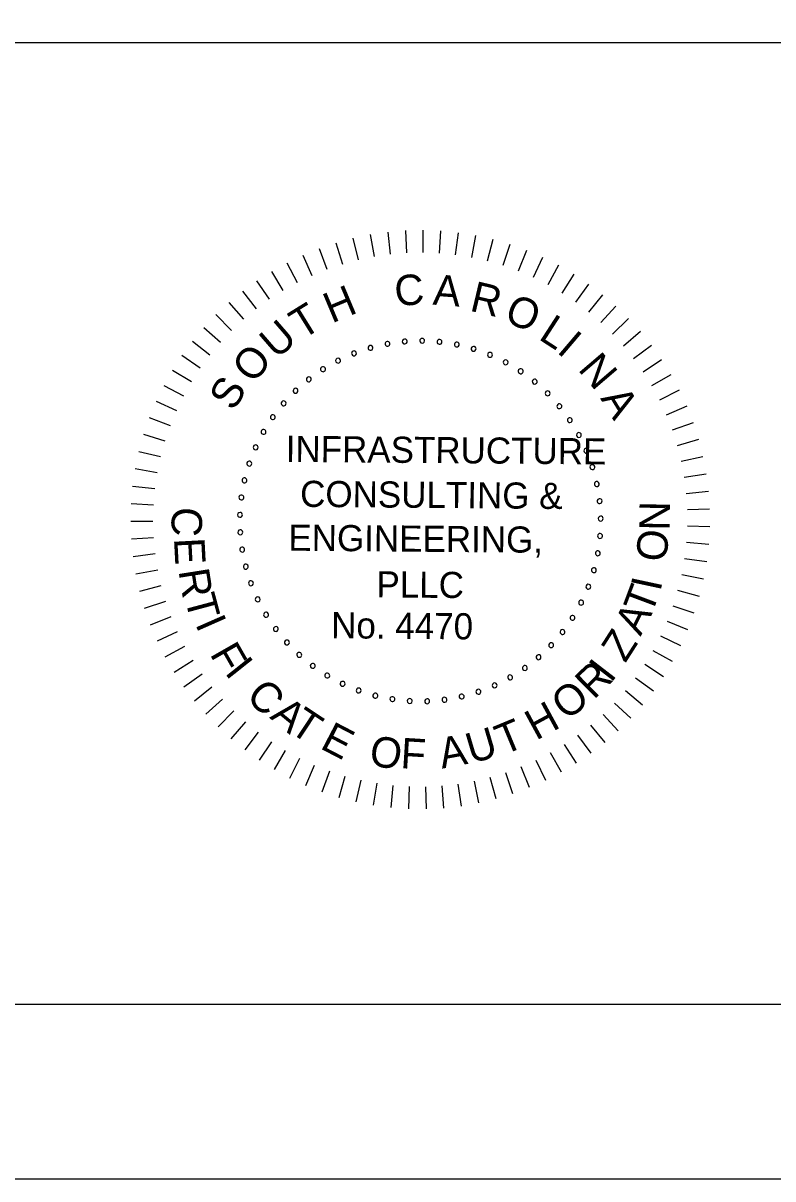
# Model space of a CAD drawing. Extents: x -121.2 to -24.9, y 6.4 to 65.9.
# Drawn here: x -53.97 to -48.25, y 6.35 to 15.17 of the extents above; entities that cross this region are included whole.
import ezdxf

# ---------------------------------------------------------------- set-up
doc = ezdxf.new("R2010")
doc.units = 0
for name, color, linetype in [('BR_BORDER LINES', 7, 'Continuous'), ('BR_TEXT', 7, 'Continuous'), ('Level 31', 7, 'Continuous')]:
    doc.layers.add(name, color=color, linetype=linetype)

msp = doc.modelspace()

# ---------------------------------------------------------------- linework, layer by layer
at = {"layer": 'BR_BORDER LINES'}
for p, q in [((-60.8035, 15.017), (-46.4963, 15.017)), ((-116.2718, 7.6833), (-26.4955, 7.6833))]:
    msp.add_line(p, q, dxfattribs=at)
at = {"layer": 'BR_TEXT'}
for p, q in [((-51.0538, 13.583), (-51.0448, 13.4135)), ((-50.9192, 13.5858), (-50.9206, 13.4161)), ((-50.7847, 13.5805), (-50.7964, 13.4111)), ((-51.583, 13.4903), (-51.5333, 13.3279)), ((-51.453, 13.5255), (-51.4134, 13.3604)), ((-51.3212, 13.5528), (-51.2917, 13.3856)), ((-51.188, 13.572), (-51.1687, 13.4033)), ((-50.6507, 13.5669), (-50.6728, 13.3985)), ((-50.5179, 13.5452), (-50.5502, 13.3785)), ((-50.3866, 13.5154), (-50.429, 13.351)), ((-51.7105, 13.4471), (-51.651, 13.2881)), ((-50.2574, 13.4777), (-50.3097, 13.3162)), ((-50.1307, 13.4322), (-50.1927, 13.2741)), ((-51.9565, 13.338), (-51.8781, 13.1874)), ((-51.8352, 13.3963), (-51.7661, 13.2412)), ((-50.007, 13.379), (-50.0786, 13.225)), ((-49.8868, 13.3184), (-49.9676, 13.1691)), ((-52.0741, 13.2724), (-51.9867, 13.1268)), ((-49.7705, 13.2506), (-49.8603, 13.1065)), ((-52.1874, 13.1997), (-52.0913, 13.0598)), ((-49.6586, 13.1758), (-49.757, 13.0374)), ((-52.2961, 13.1203), (-52.1916, 12.9865)), ((-49.5514, 13.0943), (-49.658, 12.9622)), ((-52.3997, 13.0344), (-52.2873, 12.9072)), ((-49.4494, 13.0064), (-49.5639, 12.8811)), ((-52.498, 12.9423), (-52.378, 12.8222)), ((-49.3529, 12.9125), (-49.4749, 12.7944)), ((-52.5904, 12.8445), (-52.4633, 12.7319)), ((-49.2624, 12.8129), (-49.3913, 12.7024)), ((-52.6767, 12.7411), (-52.543, 12.6365)), ((-49.178, 12.708), (-49.3135, 12.6056)), ((-52.7565, 12.6327), (-52.6167, 12.5364)), ((-52.8296, 12.5197), (-52.6841, 12.4321)), ((-49.1003, 12.5981), (-49.2417, 12.5041)), ((-49.0294, 12.4836), (-49.1763, 12.3985)), ((-52.8956, 12.4024), (-52.7451, 12.3238)), ((-48.9656, 12.3651), (-49.1174, 12.289)), ((-52.9544, 12.2812), (-52.7994, 12.212)), ((-48.9091, 12.2429), (-49.0653, 12.1762)), ((-53.0057, 12.1568), (-52.8467, 12.0971)), ((-48.8602, 12.1175), (-49.0201, 12.0604)), ((-53.0493, 12.0294), (-52.887, 11.9795)), ((-48.819, 11.9893), (-48.9821, 11.9421)), ((-53.085, 11.8996), (-52.92, 11.8597)), ((-48.7858, 11.8588), (-48.9514, 11.8217)), ((-53.1128, 11.7679), (-52.9456, 11.7381)), ((-48.7605, 11.7266), (-48.9281, 11.6996)), ((-53.1325, 11.6347), (-52.9638, 11.6152)), ((-48.7433, 11.5931), (-48.9123, 11.5764)), ((-53.144, 11.5006), (-52.9744, 11.4914)), ((-48.7344, 11.4588), (-48.904, 11.4524)), ((-53.1473, 11.366), (-52.9775, 11.3672)), ((-48.7336, 11.3241), (-48.9033, 11.3281)), ((-53.1424, 11.2314), (-52.973, 11.243)), ((-48.741, 11.1897), (-48.9102, 11.2041)), ((-53.1294, 11.0975), (-52.961, 11.1193)), ((-48.7566, 11.056), (-48.9246, 11.0806)), ((-53.1081, 10.9645), (-52.9414, 10.9966)), ((-48.7804, 10.9235), (-48.9465, 10.9583)), ((-53.0788, 10.8331), (-52.9144, 10.8753)), ((-53.0416, 10.7037), (-52.88, 10.7559)), ((-48.8121, 10.7927), (-48.9759, 10.8376)), ((-48.8518, 10.664), (-49.0125, 10.7188)), ((-52.9966, 10.5769), (-52.8384, 10.6388)), ((-48.8993, 10.538), (-49.0563, 10.6025)), ((-52.9438, 10.453), (-52.7898, 10.5244)), ((-52.8837, 10.3326), (-52.7343, 10.4132)), ((-48.9543, 10.4152), (-49.1072, 10.4891)), ((-49.0168, 10.2959), (-49.1648, 10.379)), ((-52.8163, 10.216), (-52.6721, 10.3057)), ((-49.0863, 10.1807), (-49.2291, 10.2727)), ((-52.7419, 10.1038), (-52.6034, 10.2021)), ((-49.1628, 10.0699), (-49.2997, 10.1704)), ((-52.6608, 9.9963), (-52.5286, 10.1028)), ((-49.2459, 9.964), (-49.3764, 10.0726)), ((-52.5734, 9.894), (-52.4479, 10.0084)), ((-49.3353, 9.8633), (-49.4589, 9.9797)), ((-52.4798, 9.7972), (-52.3615, 9.919)), ((-49.4307, 9.7683), (-49.547, 9.892)), ((-52.3805, 9.7063), (-52.2699, 9.8351)), ((-49.5317, 9.6793), (-49.6402, 9.8099)), ((-52.2759, 9.6216), (-52.1733, 9.7569)), ((-49.6379, 9.5966), (-49.7382, 9.7335)), ((-52.1663, 9.5434), (-52.0721, 9.6847)), ((-52.0521, 9.4721), (-51.9668, 9.6188)), ((-49.749, 9.5205), (-49.8408, 9.6633)), ((-51.9338, 9.4078), (-51.8576, 9.5595)), ((-49.984, 9.3894), (-50.0577, 9.5423)), ((-49.8645, 9.4513), (-49.9474, 9.5995)), ((-51.8118, 9.3509), (-51.745, 9.507)), ((-51.6866, 9.3016), (-51.6294, 9.4614)), ((-50.2332, 9.2878), (-50.2878, 9.4485)), ((-50.107, 9.3348), (-50.1713, 9.4919)), ((-51.5586, 9.2599), (-51.5112, 9.423)), ((-51.4282, 9.2261), (-51.3909, 9.3918)), ((-51.2961, 9.2004), (-51.2689, 9.368)), ((-51.1626, 9.1827), (-51.1457, 9.3517)), ((-50.7593, 9.1789), (-50.7734, 9.3481)), ((-50.6255, 9.194), (-50.6499, 9.3621)), ((-50.4929, 9.2173), (-50.5275, 9.3835)), ((-50.362, 9.2486), (-50.4066, 9.4124)), ((-51.0283, 9.1733), (-51.0218, 9.3429)), ((-50.8937, 9.172), (-50.8975, 9.3417))]:
    msp.add_line(p, q, dxfattribs=at)
for centre, start, end in [((-51.3195, 12.6894), 16.14222, 196.14222), ((-51.3195, 12.6894), 196.14222, 16.14222), ((-51.1901, 12.7199), 10.60376, 190.60376), ((-51.1901, 12.7199), 190.60376, 10.60376), ((-51.0585, 12.7377), 5.06529, 185.06529), ((-51.0585, 12.7377), 185.06529, 5.06529), ((-50.9257, 12.7428), 359.52683, 179.52683), ((-50.9257, 12.7428), 179.52683, 359.52683), ((-50.793, 12.735), 173.98837, 353.98837), ((-50.793, 12.735), 353.98837, 173.98837), ((-50.6617, 12.7144), 168.44991, 348.44991), ((-50.6617, 12.7144), 348.44991, 168.44991), ((-50.5331, 12.6813), 342.91145, 162.91145), ((-51.5664, 12.5918), 27.21914, 207.21914), ((-51.4453, 12.6466), 21.68068, 201.68068), ((-51.4453, 12.6466), 201.68068, 21.68068), ((-50.5331, 12.6813), 162.91145, 342.91145), ((-50.4082, 12.6359), 157.37299, 337.37299), ((-50.4082, 12.6359), 337.37299, 157.37299), ((-51.6816, 12.5256), 32.7576, 212.7576), ((-51.6816, 12.5256), 212.7576, 32.7576), ((-51.5664, 12.5918), 207.21914, 27.21914), ((-50.2882, 12.5787), 151.83453, 331.83453), ((-50.2882, 12.5787), 331.83453, 151.83453), ((-50.1744, 12.5102), 146.29606, 326.29606), ((-50.1744, 12.5102), 326.29606, 146.29606), ((-51.7899, 12.4486), 38.29606, 218.29606), ((-51.7899, 12.4486), 218.29606, 38.29606), ((-50.0677, 12.431), 140.7576, 320.7576), ((-50.0677, 12.431), 320.7576, 140.7576), ((-51.8902, 12.3615), 43.83453, 223.83453), ((-51.8902, 12.3615), 223.83453, 43.83453), ((-49.9691, 12.3418), 135.21914, 315.21914), ((-49.9691, 12.3418), 315.21914, 135.21914), ((-51.9817, 12.2651), 49.37299, 229.37299), ((-51.9817, 12.2651), 229.37299, 49.37299), ((-49.8796, 12.2436), 129.68068, 309.68068), ((-49.8796, 12.2436), 309.68068, 129.68068), ((-52.0635, 12.1604), 54.91145, 234.91145), ((-52.0635, 12.1604), 234.91145, 54.91145), ((-49.8001, 12.1372), 124.14222, 304.14222), ((-49.8001, 12.1372), 304.14222, 124.14222), ((-52.1347, 12.0482), 60.44991, 240.44991), ((-52.1347, 12.0482), 240.44991, 60.44991), ((-49.7311, 12.0236), 118.60376, 298.60376), ((-49.7311, 12.0236), 298.60376, 118.60376), ((-52.1949, 11.9297), 65.98837, 245.98837), ((-52.1949, 11.9297), 245.98837, 65.98837), ((-49.6734, 11.9039), 113.06529, 293.06529), ((-49.6734, 11.9039), 293.06529, 113.06529), ((-52.2432, 11.806), 71.52683, 251.52683), ((-52.2432, 11.806), 251.52683, 71.52683), ((-49.6276, 11.7792), 107.52683, 287.52683), ((-49.6276, 11.7792), 287.52683, 107.52683), ((-52.2795, 11.6781), 77.06529, 257.06529), ((-52.2795, 11.6781), 257.06529, 77.06529), ((-49.594, 11.6506), 101.98837, 281.98837), ((-49.594, 11.6506), 281.98837, 101.98837), ((-52.3032, 11.5474), 82.60376, 262.60376), ((-52.3032, 11.5474), 262.60376, 82.60376), ((-49.573, 11.5194), 96.44991, 276.44991), ((-49.573, 11.5194), 276.44991, 96.44991), ((-52.3142, 11.4149), 88.14222, 268.14222), ((-52.3142, 11.4149), 268.14222, 88.14222), ((-49.5647, 11.3868), 90.91145, 270.91145), ((-49.5647, 11.3868), 270.91145, 90.91145), ((-52.3123, 11.2821), 93.68068, 273.68068), ((-52.3123, 11.2821), 273.68068, 93.68068), ((-49.5693, 11.254), 85.37299, 265.37299), ((-49.5693, 11.254), 265.37299, 85.37299), ((-52.2976, 11.15), 99.21914, 279.21914), ((-52.2976, 11.15), 279.21914, 99.21914), ((-49.5866, 11.1222), 79.83453, 259.83453), ((-49.5866, 11.1222), 259.83453, 79.83453), ((-52.2703, 11.02), 104.7576, 284.7576), ((-52.2703, 11.02), 284.7576, 104.7576), ((-49.6166, 10.9928), 74.29606, 254.29606), ((-49.6166, 10.9928), 254.29606, 74.29606), ((-52.2305, 10.8932), 110.29606, 290.29606), ((-52.2305, 10.8932), 290.29606, 110.29606), ((-49.659, 10.8668), 68.7576, 248.7576), ((-49.659, 10.8668), 248.7576, 68.7576), ((-52.1787, 10.7708), 115.83453, 295.83453), ((-52.1787, 10.7708), 295.83453, 115.83453), ((-49.7133, 10.7456), 63.21914, 243.21914), ((-49.7133, 10.7456), 243.21914, 63.21914), ((-52.1153, 10.654), 121.37299, 301.37299), ((-52.1153, 10.654), 301.37299, 121.37299), ((-49.7791, 10.6301), 57.68068, 237.68068), ((-49.7791, 10.6301), 237.68068, 57.68068), ((-52.041, 10.5439), 126.91145, 306.91145), ((-52.041, 10.5439), 306.91145, 126.91145), ((-49.8557, 10.5215), 52.14222, 232.14222), ((-49.8557, 10.5215), 232.14222, 52.14222), ((-51.9563, 10.4415), 132.44991, 312.44991), ((-51.9563, 10.4415), 312.44991, 132.44991), ((-49.9424, 10.4208), 46.60376, 226.60376), ((-49.9424, 10.4208), 226.60376, 46.60376), ((-51.8622, 10.3477), 137.98837, 317.98837), ((-51.8622, 10.3477), 317.98837, 137.98837), ((-50.0384, 10.329), 41.06529, 221.06529), ((-50.0384, 10.329), 221.06529, 41.06529), ((-51.7594, 10.2634), 143.52683, 323.52683), ((-51.7594, 10.2634), 323.52683, 143.52683), ((-50.1429, 10.2468), 35.52683, 215.52683), ((-50.1429, 10.2468), 215.52683, 35.52683), ((-51.649, 10.1894), 149.06529, 329.06529), ((-51.649, 10.1894), 329.06529, 149.06529), ((-51.532, 10.1265), 334.60376, 154.60376), ((-50.2548, 10.1752), 29.98837, 209.98837), ((-50.2548, 10.1752), 209.98837, 29.98837), ((-51.532, 10.1265), 154.60376, 334.60376), ((-51.4095, 10.0751), 160.14222, 340.14222), ((-51.4095, 10.0751), 340.14222, 160.14222), ((-51.2825, 10.0358), 345.68068, 165.68068), ((-50.4966, 10.0658), 18.91145, 198.91145), ((-50.4966, 10.0658), 198.91145, 18.91145), ((-50.3731, 10.1146), 24.44991, 204.44991), ((-50.3731, 10.1146), 204.44991, 24.44991), ((-51.2825, 10.0358), 165.68068, 345.68068), ((-51.1524, 10.009), 171.21914, 351.21914), ((-51.1524, 10.009), 351.21914, 171.21914), ((-51.0203, 9.9948), 176.7576, 356.7576), ((-51.0203, 9.9948), 356.7576, 176.7576), ((-50.8874, 9.9934), 2.29606, 182.29606), ((-50.8874, 9.9934), 182.29606, 2.29606), ((-50.755, 10.0049), 7.83453, 187.83453), ((-50.755, 10.0049), 187.83453, 7.83453), ((-50.6244, 10.0291), 13.37299, 193.37299), ((-50.6244, 10.0291), 193.37299, 13.37299)]:
    msp.add_arc(centre, 0.0187, start, end, dxfattribs=at)
at = {"layer": 'Level 31'}
msp.add_lwpolyline([(-121.1606, 6.3502), (-25.1605, 6.3502), (-25.1605, 65.0169), (-121.1606, 65.0169)], close=True, dxfattribs=at)

# ---------------------------------------------------------------- texts
at = {"layer": 'BR_TEXT'}
for s, height, rotation, p in [('C', 0.2325, 4.72812, (-51.127, 13.0056)), ('A', 0.2325, 355.69809, (-50.8485, 13.0188)), ('H', 0.2325, 22.78817, (-51.6146, 12.8738)), ('R', 0.2325, 346.66807, (-50.5704, 12.9735)), ('O', 0.2325, 337.63804, (-50.3097, 12.894)), ('T', 0.2325, 31.81819, (-51.8408, 12.7468)), ('U', 0.2325, 40.84822, (-52.0363, 12.5971)), ('L', 0.2325, 327.10802, (-50.0461, 12.7595)), ('I', 0.2325, 319.578, (-49.906, 12.6586)), ('O', 0.2325, 49.87824, (-52.2149, 12.4078)), ('N', 0.2325, 310.54797, (-49.7438, 12.5232)), ('S', 0.2325, 58.90827, (-52.3628, 12.1993)), ('A', 0.2325, 301.51795, (-49.5703, 12.3035)), ('INFRASTRUCTURE', 0.19939, 359.52683, (-51.9664, 11.8192)), ('CONSULTING &', 0.19939, 359.52683, (-51.8563, 11.4762)), ('N', 0.2325, 89.20849, (-49.0389, 11.2935)), ('C', 0.2325, 267.02504, (-52.8294, 11.4795)), ('ENGINEERING,', 0.19939, 359.52683, (-51.9459, 11.1418)), ('O', 0.2325, 83.20849, (-49.0684, 11.0496)), ('E', 0.2325, 273.02504, (-52.8177, 11.2353)), ('R', 0.2325, 279.02504, (-52.7836, 10.9892)), ('PLLC', 0.19939, 359.52683, (-51.2747, 10.7856)), ('T', 0.2325, 69.39539, (-49.1783, 10.6448)), ('I', 0.2325, 77.90926, (-49.1098, 10.8248)), ('T', 0.2325, 285.02504, (-52.7372, 10.7791)), ('No. 4470', 0.19939, 359.52683, (-51.6201, 10.4739)), ('A', 0.2325, 63.39539, (-49.2604, 10.4839)), ('I', 0.2325, 293.77127, (-52.658, 10.5842)), ('Z', 0.2325, 57.39539, (-49.3773, 10.2803)), ('F', 0.2325, 299.77127, (-52.5482, 10.3547)), ('I', 0.2325, 308.52683, (-52.4359, 10.2111)), ('R', 0.2325, 44.52683, (-49.6185, 10.0004)), ('I', 0.2325, 52.33388, (-49.4869, 10.1265)), ('C', 0.2325, 314.52683, (-52.2776, 10.0241)), ('O', 0.2325, 38.52683, (-49.8227, 9.8405)), ('A', 0.2325, 320.52683, (-52.0932, 9.8679)), ('H', 0.2325, 28.52683, (-50.0577, 9.6912)), ('T', 0.2325, 326.52683, (-51.948, 9.7653)), ('E', 0.2325, 332.52683, (-51.7118, 9.6378)), ('U', 0.2325, 16.52683, (-50.5508, 9.5148)), ('T', 0.2325, 22.52683, (-50.3062, 9.5798)), ('O', 0.2325, 350.52683, (-51.3381, 9.5075)), ('F', 0.2325, 356.52683, (-51.0943, 9.4832)), ('A', 0.2325, 10.52683, (-50.7746, 9.4788))]:
    msp.add_text(s, height=height, rotation=rotation, dxfattribs=at).set_placement(p)

doc.saveas('drawing.dxf')
